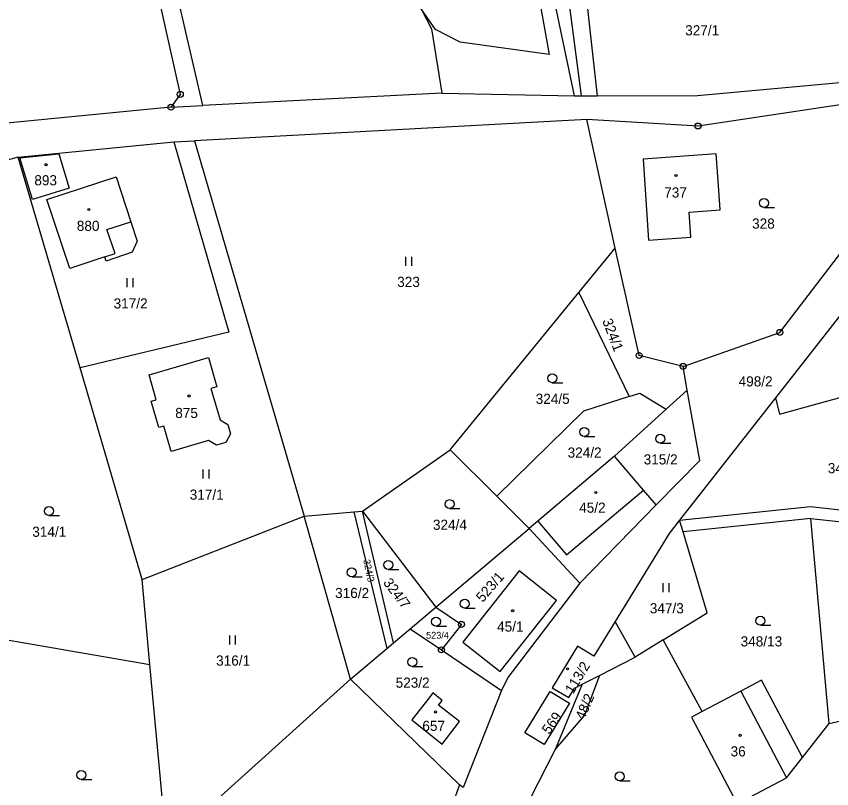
# Model space of a CAD drawing. Extents: x -725728 to -720881, y -1068679 to -1063504.
# Drawn here: x -724517 to -724380.5, y -1066931.7 to -1066802.4 of the extents above; entities that cross this region are included whole.
import ezdxf

# ---------------------------------------------------------------- set-up
doc = ezdxf.new("R2010")
doc.units = 0
for name, color, linetype in [('Hranice parcel', 7, 'Continuous'), ('Parcelní čísla', 7, 'Continuous'), ('Vnitřní kresba', 7, 'Continuous'), ('Značky bodu BP', 7, 'Continuous'), ('Značky budov', 7, 'Continuous'), ('Značky kultur', 7, 'Continuous')]:
    doc.layers.add(name, color=color, linetype=linetype)

# ---------------------------------------------------------------- blocks, each defined once
blk = doc.blocks.new('4.02_3')
at = {"layer": 'Značky budov'}
blk.add_circle((-0.001, 0), 0.0175, dxfattribs=at)
blk = doc.blocks.new('4.02_4')
at = {"layer": 'Značky budov'}
blk.add_circle((-0.001, 0), 0.0175, dxfattribs=at)
blk = doc.blocks.new('3.04_2')
at = {"layer": 'Značky kultur'}
blk.add_line((0.001, 0), (0.176, 0), dxfattribs=at)
blk.add_circle((0.001, 0.075), 0.075, dxfattribs=at)
blk = doc.blocks.new('3.04_3')
at = {"layer": 'Značky kultur'}
blk.add_line((0.001, 0), (0.176, 0), dxfattribs=at)
blk.add_circle((0.001, 0.075), 0.075, dxfattribs=at)
blk = doc.blocks.new('3.06_1')
at = {"layer": 'Značky kultur'}
for p, q in [((-0.051, 0), (-0.051, 0.15)), ((0.049, 0), (0.049, 0.15))]:
    blk.add_line(p, q, dxfattribs=at)
blk = doc.blocks.new('1.05_1')
at = {"layer": 'Značky bodu BP'}
for radius in [0.05, 0.00303]:
    blk.add_circle((0, 0), radius, dxfattribs=at)
blk = doc.blocks.new('1.05_2')
at = {"layer": 'Značky bodu BP'}
for radius in [0.05, 0.00303]:
    blk.add_circle((0, 0), radius, dxfattribs=at)

msp = doc.modelspace()

# ---------------------------------------------------------------- linework, layer by layer
at = {"layer": 'Hranice parcel'}
for p, q in [((-724485.75, -1066817.35), (-724493.89, -1066782.53)), ((-724423.59, -1066815.74), (-724428.99, -1066789.95)), ((-724445.77, -1066815.34), (-724485.75, -1066817.35)), ((-724445.77, -1066815.34), (-724423.59, -1066815.74)), ((-724423.59, -1066815.74), (-724422.43, -1066815.76)), ((-724422.43, -1066815.76), (-724419.79, -1066815.75)), ((-724491.11, -1066817.66), (-724519.12, -1066820.4)), ((-724491.11, -1066817.66), (-724485.75, -1066817.35)), ((-724378.02, -1066817.12), (-724402.91, -1066820.81)), ((-724421.53, -1066819.7), (-724487.16, -1066823.29)), ((-724402.91, -1066820.81), (-724421.53, -1066819.7)), ((-724416.76, -1066841.26), (-724421.53, -1066819.7)), ((-724516.69, -1066826.04), (-724490.64, -1066823.47)), ((-724490.64, -1066823.47), (-724487.16, -1066823.29)), ((-724487.16, -1066823.29), (-724468.79, -1066886.12)), ((-724516.69, -1066826.04), (-724532.8, -1066830.49)), ((-724506.28, -1066861.3), (-724516.69, -1066826.04)), ((-724422.84, -1066848.69), (-724416.76, -1066841.26)), ((-724412.77, -1066859.22), (-724416.76, -1066841.26)), ((-724444.37, -1066875.01), (-724422.84, -1066848.69)), ((-724422.84, -1066848.69), (-724414.43, -1066866.11)), ((-724405.4, -1066861.04), (-724412.77, -1066859.22)), ((-724495.94, -1066896.7), (-724506.28, -1066861.3)), ((-724404.7, -1066865.01), (-724405.4, -1066861.04)), ((-724404.7, -1066865.01), (-724408.24, -1066868.22)), ((-724389.94, -1066866.29), (-724406, -1066886.8)), ((-724408.24, -1066868.22), (-724416.88, -1066876.06)), ((-724459.04, -1066885.27), (-724444.37, -1066875.01)), ((-724436.58, -1066882.79), (-724444.37, -1066875.01)), ((-724436.58, -1066882.79), (-724431.16, -1066888.19)), ((-724422.71, -1066897.34), (-724409.9, -1066884.23)), ((-724468.79, -1066886.12), (-724460.53, -1066885.4)), ((-724460.53, -1066885.4), (-724459.04, -1066885.27)), ((-724460.53, -1066885.4), (-724455.01, -1066908.29)), ((-724453.86, -1066907.32), (-724459.04, -1066885.27)), ((-724459.04, -1066885.27), (-724446.76, -1066901.33)), ((-724495.94, -1066896.7), (-724468.79, -1066886.12)), ((-724461.04, -1066913.37), (-724468.79, -1066886.12)), ((-724405.42, -1066888.75), (-724406, -1066886.8)), ((-724384.05, -1066886.51), (-724405.42, -1066888.75)), ((-724380.97, -1066920.82), (-724384.05, -1066886.51)), ((-724384.05, -1066886.51), (-724363.99, -1066888.62)), ((-724446.76, -1066901.33), (-724431.16, -1066888.19)), ((-724431.16, -1066888.19), (-724422.71, -1066897.34)), ((-724494.67, -1066910.94), (-724495.94, -1066896.7)), ((-724451.06, -1066904.96), (-724446.76, -1066901.33)), ((-724453.86, -1066907.32), (-724451.06, -1066904.96)), ((-724451.06, -1066904.96), (-724445.86, -1066908.49)), ((-724413.45, -1066909.72), (-724416.76, -1066903.75)), ((-724522.89, -1066906.08), (-724494.67, -1066910.94)), ((-724455.01, -1066908.29), (-724453.86, -1066907.32)), ((-724408.72, -1066906.8), (-724413.45, -1066909.72)), ((-724402.2, -1066918.82), (-724408.72, -1066906.8)), ((-724461.04, -1066913.37), (-724455.01, -1066908.29)), ((-724445.86, -1066908.49), (-724435.79, -1066915.32)), ((-724419.42, -1066912.78), (-724413.45, -1066909.72)), ((-724491.79, -1066941.15), (-724494.67, -1066910.94)), ((-724422.28, -1066914.25), (-724419.42, -1066912.78)), ((-724482.71, -1066932.92), (-724461.04, -1066913.37)), ((-724442.81, -1066931.06), (-724461.04, -1066913.37)), ((-724422.28, -1066914.25), (-724426.78, -1066925.03)), ((-724380.97, -1066920.82), (-724353.55, -1066914.58)), ((-724385.43, -1066926.5), (-724380.97, -1066920.82))]:
    msp.add_line(p, q, dxfattribs=at)
for points in [[(-724493.89, -1066782.53), (-724478.66, -1066775.94), (-724466.97, -1066779.51), (-724453.45, -1066790.66), (-724449.23, -1066801.21), (-724447.5, -1066804.52), (-724445.77, -1066815.34)], [(-724496.84, -1066783.09), (-724489.55, -1066815.52), (-724491.11, -1066817.66)], [(-724422.43, -1066815.76), (-724425.99, -1066788.5), (-724426.52, -1066784.86)], [(-724449.23, -1066801.21), (-724450.14, -1066796.78), (-724449.23, -1066792.38), (-724446.26, -1066788.89), (-724442.03, -1066787.29), (-724437.63, -1066787.34), (-724433.31, -1066789.3), (-724430.68, -1066792.92), (-724427.8, -1066808.84), (-724442.72, -1066806.78), (-724446.82, -1066804.64), (-724449.23, -1066801.21)], [(-724422.38, -1066792.51), (-724420.91, -1066805.71), (-724419.79, -1066815.75)], [(-724419.79, -1066815.75), (-724402.97, -1066815.71), (-724378.57, -1066813.49)], [(-724490.64, -1066823.47), (-724481.41, -1066855.33), (-724506.28, -1066861.3)], [(-724514.29, -1066833.1), (-724516.39, -1066826.14), (-724509.87, -1066825.45), (-724508.14, -1066831.23), (-724514.29, -1066833.1)], [(-724399.87, -1066825.47), (-724412.07, -1066826.35), (-724411.21, -1066839.92), (-724404.1, -1066839.43), (-724404.37, -1066835.22), (-724399.19, -1066834.84), (-724399.43, -1066831.54), (-724399.87, -1066825.47)], [(-724405.4, -1066861.04), (-724389.22, -1066855.35), (-724377.57, -1066840.15), (-724371.59, -1066827.9)], [(-724508.04, -1066844.66), (-724511.86, -1066833.13), (-724500.28, -1066829.3), (-724497.84, -1066836.83), (-724496.79, -1066840.09), (-724497.6, -1066841.9), (-724501.94, -1066843.42), (-724502.19, -1066842.71), (-724508.04, -1066844.66)], [(-724361.86, -1066829.53), (-724377.64, -1066850.59), (-724389.94, -1066866.29)], [(-724389.94, -1066866.29), (-724389.27, -1066869.02), (-724347.74, -1066857.59)], [(-724494.4, -1066866.87), (-724493.57, -1066866.63), (-724494.76, -1066862.44), (-724484.8, -1066859.58), (-724483.41, -1066864.45), (-724484.41, -1066864.73), (-724482.89, -1066870.01), (-724481.57, -1066870.76), (-724481.12, -1066872.33), (-724481.92, -1066873.77), (-724483.49, -1066874.22), (-724484.81, -1066873.47), (-724491.1, -1066875.28), (-724492.3, -1066871.05), (-724493.12, -1066871.28), (-724494.4, -1066866.87)], [(-724409.9, -1066884.23), (-724402.62, -1066876.78), (-724404.7, -1066865.01)], [(-724414.43, -1066866.11), (-724422.05, -1066868.54), (-724436.58, -1066882.79)], [(-724414.43, -1066866.11), (-724412.66, -1066865.54), (-724408.24, -1066868.22)], [(-724416.88, -1066876.06), (-724429.72, -1066886.97), (-724431.16, -1066888.19)], [(-724409.9, -1066884.23), (-724412.01, -1066881.76), (-724416.88, -1066876.06)], [(-724406, -1066886.8), (-724384.06, -1066884.5), (-724342.28, -1066889.18)], [(-724406, -1066886.8), (-724407.72, -1066888.99), (-724416.76, -1066903.75)], [(-724408.72, -1066906.8), (-724401.39, -1066902.27), (-724405.42, -1066888.75)], [(-724426.57, -1066900.25), (-724432.82, -1066895.26), (-724442.28, -1066907.19), (-724436.03, -1066912.13), (-724426.57, -1066900.25)], [(-724422.71, -1066897.34), (-724434.71, -1066913.1), (-724435.79, -1066915.32)], [(-724446.76, -1066901.33), (-724442.49, -1066904.23), (-724445.86, -1066908.49)], [(-724416.76, -1066903.75), (-724420.32, -1066909.57), (-724423.1, -1066907.88), (-724427.34, -1066914.85), (-724424.53, -1066916.49), (-724423.58, -1066914.92), (-724422.28, -1066914.25)], [(-724419.42, -1066912.78), (-724421.93, -1066919.43), (-724426.78, -1066925.03)], [(-724385.43, -1066926.5), (-724392.27, -1066913.57), (-724395.77, -1066915.42), (-724402.2, -1066918.82)], [(-724445.71, -1066924.28), (-724442.84, -1066920.51), (-724446.34, -1066917.76), (-724445.72, -1066916.97), (-724447.28, -1066915.71), (-724447.92, -1066916.52), (-724450.82, -1066920.22), (-724445.71, -1066924.28)], [(-724435.79, -1066915.32), (-724442.19, -1066931.51), (-724442.81, -1066931.06)], [(-724428.67, -1066924.33), (-724431.87, -1066922.37), (-724427.64, -1066915.45), (-724424.44, -1066917.41), (-724428.67, -1066924.33)], [(-724402.2, -1066918.82), (-724404.01, -1066919.78), (-724396.34, -1066934.27)], [(-724426.78, -1066925.03), (-724436.84, -1066944.86), (-724455.08, -1066967.44)], [(-724396.34, -1066934.27), (-724388.1, -1066929.91), (-724385.43, -1066926.5)], [(-724442.81, -1066931.06), (-724445.18, -1066937.54), (-724458.08, -1066957.97), (-724467.52, -1066969.09)]]:
    msp.add_lwpolyline(points, dxfattribs=at)
at = {"layer": 'Vnitřní kresba'}
for p, q in [((-724501.83, -1066838.12), (-724497.84, -1066836.83)), ((-724500.46, -1066842.14), (-724501.83, -1066838.12)), ((-724502.19, -1066842.71), (-724500.46, -1066842.14)), ((-724424.93, -1066892.61), (-724412.01, -1066881.76)), ((-724429.72, -1066886.97), (-724424.93, -1066892.61)), ((-724395.77, -1066915.42), (-724388.1, -1066929.91))]:
    msp.add_line(p, q, dxfattribs=at)

# ---------------------------------------------------------------- block references
at = {"layer": 'Značky bodu BP', "xscale": 10, "yscale": 10}
for name, p in [('1.05_1', (-724489.55, -1066815.52)), ('1.05_2', (-724491.11, -1066817.66)), ('1.05_1', (-724402.91, -1066820.81)), ('1.05_1', (-724389.22, -1066855.35)), ('1.05_1', (-724412.77, -1066859.22)), ('1.05_1', (-724405.4, -1066861.04)), ('1.05_1', (-724442.49, -1066904.23)), ('1.05_1', (-724445.86, -1066908.49))]:
    msp.add_blockref(name, p, dxfattribs=at)
at = {"layer": 'Značky budov', "xscale": 10, "yscale": 10}
for name, p in [('4.02_3', (-724512, -1066827.29)), ('4.02_3', (-724406.59, -1066829.1)), ('4.02_3', (-724504.85, -1066834.78)), ('4.02_3', (-724488.08, -1066865.99)), ('4.02_4', (-724419.99, -1066882.16)), ('4.02_3', (-724433.91, -1066901.94)), ('4.02_4', (-724424.74, -1066911.67)), ('4.02_4', (-724446.84, -1066918.89)), ('4.02_3', (-724395.86, -1066922.8))]:
    msp.add_blockref(name, p, dxfattribs=at)
at = {"layer": 'Značky kultur', "xscale": 10, "yscale": 10}
for name, p in [('3.04_2', (-724391.89, -1066834.44)), ('3.06_1', (-724451.28, -1066844.2)), ('3.06_1', (-724497.93, -1066847.8)), ('3.04_2', (-724427.3, -1066863.77)), ('3.04_2', (-724421.96, -1066872.77)), ('3.04_3', (-724409.24, -1066873.91)), ('3.06_1', (-724485.19, -1066879.81)), ('3.04_2', (-724511.53, -1066886.02)), ('3.04_2', (-724444.5, -1066884.85)), ('3.04_2', (-724454.76, -1066895.02)), ('3.04_2', (-724460.87, -1066896.27)), ('3.06_1', (-724408.21, -1066898.83)), ('3.04_2', (-724441.95, -1066901.53)), ('3.04_2', (-724446.75, -1066904.52)), ('3.04_2', (-724392.48, -1066904.37)), ('3.06_1', (-724480.77, -1066907.58)), ('3.04_2', (-724450.74, -1066911.28)), ('3.04_2', (-724506.12, -1066930.19)), ('3.04_3', (-724416.02, -1066930.43))]:
    msp.add_blockref(name, p, dxfattribs=at)

# ---------------------------------------------------------------- texts
at = {"layer": 'Parcelní čísla'}
for s, height, p in [('327/1', 1.7, (-724405.06, -1066805.64)), ('893', 1.7, (-724513.97, -1066830.74)), ('737', 1.7, (-724408.56, -1066832.78)), ('880', 1.7, (-724506.86, -1066838.37)), ('328', 1.7, (-724393.86, -1066837.99)), ('323', 1.7, (-724453.25, -1066847.75)), ('317/2', 1.7, (-724500.7, -1066851.35)), ('498/2', 1.7, (-724396.11, -1066864.4)), ('324/5', 1.7, (-724430.07, -1066867.32)), ('875', 1.7, (-724490.39, -1066869.69)), ('324/2', 1.7, (-724424.73, -1066876.32)), ('315/2', 1.7, (-724412.01, -1066877.46)), ('348/15', 1.7, (-724381.19, -1066878.93)), ('317/1', 1.7, (-724487.97, -1066883.36)), ('45/2', 1.7, (-724422.8, -1066885.54)), ('324/4', 1.7, (-724447.27, -1066888.4)), ('314/1', 1.7, (-724514.31, -1066889.57)), ('316/2', 1.7, (-724463.64, -1066899.82)), ('347/3', 1.7, (-724410.98, -1066902.38)), ('45/1', 1.7, (-724436.53, -1066905.44)), ('523/4', 1.14, (-724448.41, -1066906.62)), ('348/13', 1.7, (-724395.78, -1066907.92)), ('316/1', 1.7, (-724483.55, -1066911.13)), ('523/2', 1.7, (-724453.51, -1066914.83)), ('657', 1.7, (-724449.04, -1066922.06)), ('36', 1.7, (-724397.46, -1066926.33))]:
    msp.add_text(s, height=height, dxfattribs=at).set_placement(p)
for s, height, rotation, p in [('324/1', 1.7, 291, (-724418.96, -1066853.4)), ('324/3', 1.14, 282, (-724458.93, -1066893.49)), ('324/7', 1.7, 307, (-724455.69, -1066897.26)), ('523/1', 1.7, 49, (-724438.95, -1066900.65)), ('113/2', 1.7, 59, (-724423.83, -1066916)), ('48/2', 1.7, 67, (-724421.95, -1066920.35)), ('569', 1.7, 54, (-724427.81, -1066922.76))]:
    msp.add_text(s, height=height, rotation=rotation, dxfattribs=at).set_placement(p)

doc.saveas('drawing.dxf')
